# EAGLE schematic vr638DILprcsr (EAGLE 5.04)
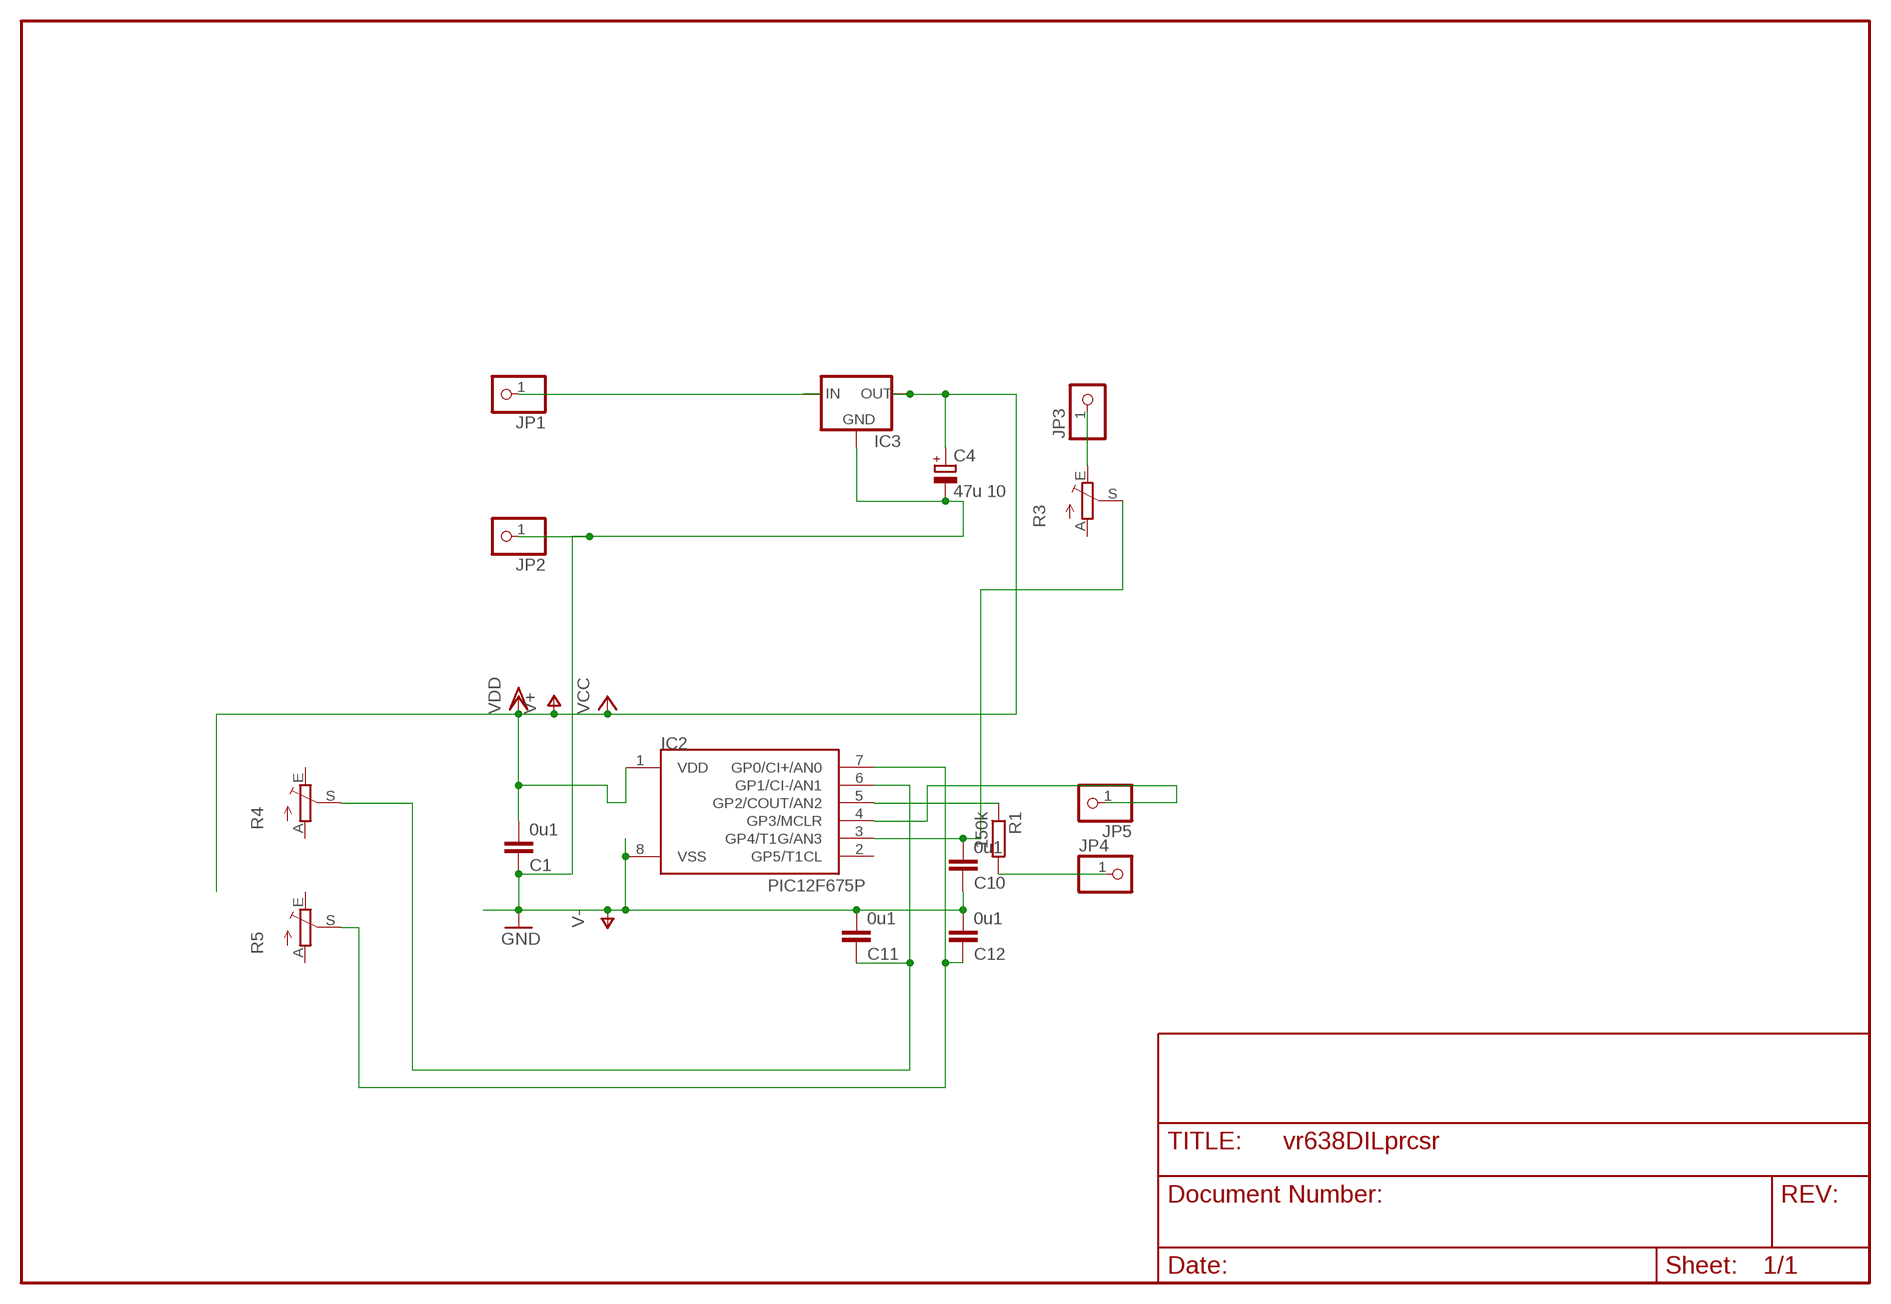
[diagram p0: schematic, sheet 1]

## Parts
C1  0u1  C-EUC1206  [C1206]
C4  47u 10  CPOL-EUE2.5-6  [E2,5-6]
C10  0u1  C-EUC1206  [C1206]
C11  0u1  C-EUC1206  [C1206]
C12  0u1  C-EUC1206  [C1206]
IC2  PIC12F675P  [DIL8]
IC3  78LXX  [78LXX]
JP1  PINHD-1X1  [1X01]
JP2  PINHD-1X1  [1X01]
JP3  PINHD-1X1  [1X01]
JP4  PINHD-1X1  [1X01]
JP5  PINHD-1X1  [1X01]
R1  150k  R-EU_R1206  [R1206]
R3  TRIM_EU-CA6V  [CA6V]
R4  TRIM_EU-CA6V  [CA6V]
R5  TRIM_EU-CA6V  [CA6V]

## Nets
N$1: JP3.1 R3.E
N$2: JP4.1 R1.2
N$3: IC2.4(GP3/MCLR) JP5.1
N$5: IC2.5(GP2/COUT/AN2) R1.1
N$12: C10.2 IC2.3(GP4/T1G/AN3) R3.S
N$13: C12.1 IC2.7(GP0/CI+/AN0) R5.S
N$15: C11.1 IC2.6(GP1/CI-/AN1) R4.S
N$20: IC3.IN JP1.1
V+: C1.2 C4.+ IC2.1(VDD) IC3.OUT ; supply symbol labelled VCC, VDD
V-: C1.1 C4.- C10.1 C11.2 C12.2 IC2.8(VSS) IC3.GND JP2.1 ; supply symbol labelled GND
Unconnected: IC2.2(GP5/T1CL) R3.A R4.A R4.E R5.A R5.E

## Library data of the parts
C1 C10-C12 = rcl:C-EU: CAPACITOR, European symbol
C4 = rcl:CPOL-EU: POLARIZED CAPACITOR, European symbol
IC2 = microchip-3:PIC12F6*: uPC nW 1k Program Flash memory 2x Timer Comparator 10b A/D converter/ 4xIN
IC3 = v-reg:78LXX: VOLTAGE REGULATOR
JP1-JP5 = pinhead:PINHD-1X1: PIN HEADER
R1 = rcl:R-EU_: RESISTOR, European symbol
R3-R5 = pot:TRIM_EU-: POTENTIOMETER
